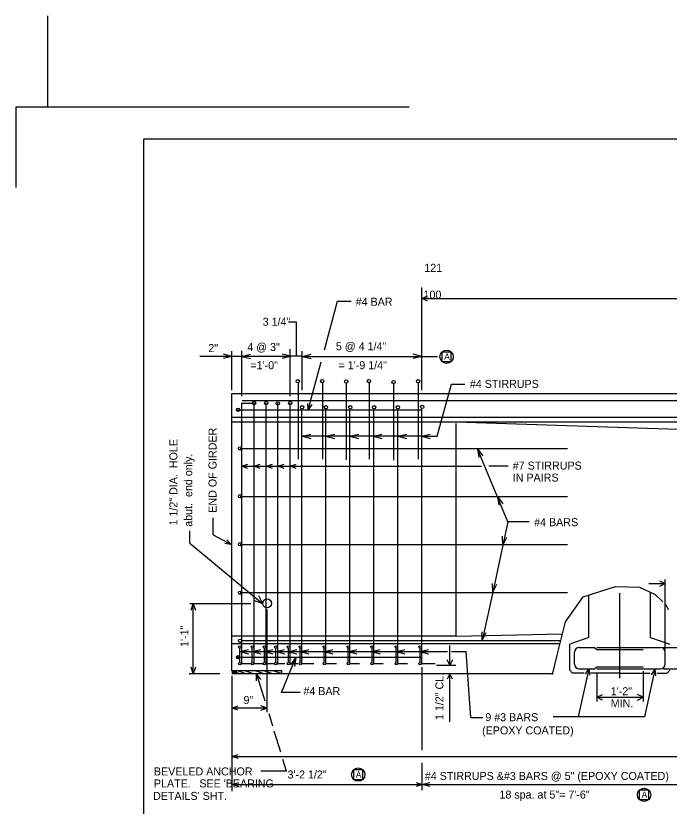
# Model space of a CAD drawing. Extents: x 1005.2 to 1101.8, y 2006.5 to 2073.7.
# Drawn here: x 1008.43 to 1035.67, y 2040.78 to 2073.7 of the extents above; entities that cross this region are included whole.
import ezdxf

# ---------------------------------------------------------------- set-up
doc = ezdxf.new("R2010")
doc.units = 0
for name, color, linetype in [('Level 1', 7, 'Continuous'), ('Level 2', 7, 'Continuous'), ('Level 5', 7, 'Continuous'), ('Level 6', 7, 'Continuous'), ('Level 60', 7, 'Continuous')]:
    doc.layers.add(name, color=color, linetype=linetype)

msp = doc.modelspace()

# ---------------------------------------------------------------- linework, layer by layer
at = {"layer": 'Level 1'}
for p, q in [((1024.831, 2069.894), (1008.43, 2069.894)), ((1008.43, 2069.894), (1008.43, 2066.554)), ((1013.763, 2012.562), (1013.763, 2068.561)), ((1097.431, 2068.561), (1013.763, 2068.561))]:
    msp.add_line(p, q, dxfattribs=at)
at = {"layer": 'Level 2'}
for p, q in [((1009.763, 2069.894), (1009.763, 2073.698)), ((1025.357, 2058.113), (1025.357, 2062.376)), ((1021.298, 2059.783), (1021.846, 2061.808)), ((1021.846, 2061.808), (1022.41, 2061.808)), ((1025.357, 2061.923), (1054.324, 2061.923)), ((1020.13, 2060.939), (1019.792, 2060.939)), ((1020.13, 2059.522), (1020.13, 2060.939)), ((1019.87, 2057.862), (1019.87, 2059.809)), ((1017.857, 2059.514), (1016.107, 2059.514)), ((1017.441, 2059.514), (1016.171, 2059.514)), ((1017.441, 2059.514), (1017.081, 2059.604)), ((1017.441, 2059.514), (1017.081, 2059.424)), ((1017.441, 2058.106), (1017.441, 2059.732)), ((1017.857, 2057.854), (1017.857, 2059.744)), ((1017.857, 2059.514), (1018.217, 2059.604)), ((1019.87, 2059.514), (1017.857, 2059.514)), ((1017.857, 2059.514), (1018.217, 2059.424)), ((1019.898, 2059.522), (1019.538, 2059.612)), ((1019.898, 2059.522), (1019.538, 2059.432)), ((1020.36, 2059.522), (1019.87, 2059.522)), ((1020.36, 2058.103), (1020.36, 2059.725)), ((1020.36, 2059.514), (1026.005, 2059.514)), ((1020.375, 2059.514), (1020.735, 2059.604)), ((1020.375, 2059.514), (1020.735, 2059.424)), ((1025.357, 2059.514), (1024.997, 2059.604)), ((1025.357, 2059.514), (1024.997, 2059.424)), ((1020.621, 2057.286), (1021.163, 2059.286)), ((1026.195, 2059.303), (1026.195, 2059.303)), ((1020.194, 2058.425), (1020.194, 2055.229)), ((1021.21, 2058.425), (1021.21, 2055.229)), ((1022.207, 2058.404), (1022.207, 2055.208)), ((1023.161, 2058.425), (1023.161, 2055.229)), ((1024.178, 2058.383), (1024.178, 2055.187)), ((1025.195, 2058.425), (1025.195, 2055.229)), ((1025.994, 2056.185), (1026.584, 2058.362)), ((1026.584, 2058.362), (1027.147, 2058.362)), ((1017.441, 2046.413), (1017.441, 2057.969)), ((1017.441, 2057.969), (1038.737, 2057.969)), ((1017.857, 2057.562), (1018.382, 2057.562)), ((1017.857, 2047.379), (1017.857, 2057.562)), ((1017.863, 2057.676), (1031.429, 2057.676)), ((1018.362, 2046.728), (1018.362, 2057.562)), ((1018.87, 2046.728), (1018.87, 2057.562)), ((1019.357, 2046.728), (1019.357, 2057.562)), ((1019.87, 2046.728), (1019.87, 2057.562)), ((1031.429, 2057.676), (1038.745, 2057.676)), ((1017.64, 2057.286), (1025.357, 2057.286)), ((1020.357, 2046.728), (1020.357, 2057.335)), ((1021.357, 2046.728), (1021.357, 2057.335)), ((1022.357, 2046.728), (1022.357, 2057.325)), ((1023.357, 2046.728), (1023.357, 2057.335)), ((1024.357, 2046.728), (1024.357, 2057.325)), ((1025.357, 2046.728), (1025.357, 2057.335)), ((1038.745, 2056.969), (1017.439, 2056.969)), ((1038.737, 2056.772), (1017.426, 2056.772)), ((1038.441, 2056.386), (1026.782, 2056.772)), ((1026.782, 2047.859), (1026.782, 2056.719)), ((1020.374, 2056.185), (1020.734, 2056.275)), ((1022.351, 2056.185), (1020.374, 2056.185)), ((1020.374, 2056.185), (1020.734, 2056.095)), ((1021.349, 2056.185), (1021.709, 2056.275)), ((1021.349, 2056.185), (1021.709, 2056.095)), ((1022.351, 2056.185), (1022.711, 2056.275)), ((1023.284, 2056.185), (1022.351, 2056.185)), ((1022.351, 2056.185), (1022.711, 2056.095)), ((1023.333, 2056.185), (1023.284, 2056.185)), ((1023.333, 2056.185), (1023.693, 2056.275)), ((1024.362, 2056.185), (1023.333, 2056.185)), ((1023.333, 2056.185), (1023.693, 2056.095)), ((1024.362, 2056.185), (1024.722, 2056.275)), ((1025.347, 2056.185), (1024.362, 2056.185)), ((1024.362, 2056.185), (1024.722, 2056.095)), ((1025.347, 2056.185), (1025.707, 2056.275)), ((1025.347, 2056.185), (1025.994, 2056.185)), ((1025.347, 2056.185), (1025.707, 2056.095)), ((1017.78, 2055.676), (1031.429, 2055.676)), ((1028.945, 2052.627), (1027.669, 2055.663)), ((1027.669, 2055.663), (1027.892, 2055.366)), ((1027.669, 2055.663), (1027.726, 2055.296)), ((1017.842, 2054.936), (1027.842, 2054.936)), ((1028.958, 2054.936), (1028.149, 2054.936)), ((1017.78, 2053.676), (1031.429, 2053.676)), ((1028.504, 2053.676), (1028.726, 2053.379)), ((1028.504, 2053.676), (1028.561, 2053.31)), ((1016.66, 2052.086), (1016.66, 2052.795)), ((1028.945, 2052.627), (1028.735, 2051.653)), ((1029.834, 2052.627), (1028.945, 2052.627)), ((1016.66, 2052.086), (1017.41, 2051.679)), ((1028.735, 2051.653), (1028.723, 2052.024)), ((1028.735, 2051.653), (1028.899, 2051.986)), ((1017.78, 2051.676), (1031.429, 2051.676)), ((1028.735, 2051.653), (1028.311, 2049.688)), ((1035.494, 2047.271), (1035.494, 2050.224)), ((1028.311, 2049.688), (1028.299, 2050.059)), ((1028.311, 2049.688), (1028.475, 2050.021)), ((1034.813, 2050.053), (1035.494, 2050.053)), ((1017.78, 2049.676), (1023.804, 2049.676)), ((1023.804, 2049.676), (1031.429, 2049.676)), ((1028.311, 2049.688), (1027.876, 2047.676)), ((1032.321, 2047.81), (1032.321, 2049.575)), ((1033.607, 2046.105), (1033.607, 2049.645)), ((1034.892, 2047.81), (1034.892, 2049.686)), ((1026.782, 2047.859), (1031.222, 2047.964)), ((1027.876, 2047.676), (1027.864, 2048.047)), ((1027.876, 2047.676), (1028.04, 2048.009)), ((1026.782, 2047.859), (1017.441, 2047.859)), ((1017.85, 2047.676), (1031.149, 2047.676)), ((1032.321, 2047.81), (1031.518, 2047.528)), ((1034.892, 2047.81), (1035.695, 2047.528)), ((1017.44, 2047.552), (1031.118, 2047.552)), ((1017.769, 2046.782), (1017.769, 2047.355)), ((1017.769, 2047.216), (1018.129, 2047.306)), ((1017.857, 2046.728), (1017.857, 2047.379)), ((1018.28, 2047.216), (1018.64, 2047.306)), ((1018.284, 2046.782), (1018.284, 2047.355)), ((1018.789, 2047.216), (1019.149, 2047.306)), ((1018.793, 2046.782), (1018.793, 2047.355)), ((1019.265, 2047.216), (1019.625, 2047.306)), ((1019.271, 2046.782), (1019.271, 2047.355)), ((1019.79, 2047.215), (1020.15, 2047.305)), ((1019.793, 2046.782), (1019.793, 2047.355)), ((1020.283, 2047.216), (1020.643, 2047.306)), ((1020.286, 2046.782), (1020.286, 2047.355)), ((1021.289, 2046.782), (1021.289, 2047.355)), ((1021.29, 2047.216), (1021.65, 2047.306)), ((1022.289, 2046.782), (1022.289, 2047.379)), ((1022.289, 2047.216), (1022.649, 2047.306)), ((1023.258, 2047.216), (1023.618, 2047.306)), ((1023.278, 2046.782), (1023.278, 2047.379)), ((1024.289, 2046.782), (1024.289, 2047.379)), ((1024.289, 2047.216), (1024.649, 2047.306)), ((1025.274, 2047.22), (1025.634, 2047.31)), ((1025.284, 2046.782), (1025.284, 2047.379)), ((1026.512, 2047.469), (1026.512, 2046.649)), ((1031.518, 2046.444), (1031.518, 2047.528)), ((1031.912, 2047.388), (1032.556, 2047.388)), ((1032.556, 2047.388), (1032.651, 2047.311)), ((1032.651, 2047.388), (1035.302, 2047.388)), ((1032.651, 2047.311), (1034.583, 2047.311)), ((1035.41, 2047.388), (1037.062, 2047.388)), ((1017.64, 2046.986), (1025.357, 2046.986)), ((1017.769, 2047.216), (1018.53, 2047.216)), ((1017.769, 2047.216), (1018.129, 2047.126)), ((1018.28, 2047.216), (1018.64, 2047.126)), ((1018.53, 2047.216), (1019.251, 2047.216)), ((1018.789, 2047.216), (1019.149, 2047.126)), ((1019.251, 2047.216), (1020.274, 2047.216)), ((1019.265, 2047.216), (1019.625, 2047.126)), ((1019.499, 2045.521), (1020.103, 2046.973)), ((1019.79, 2047.215), (1020.15, 2047.125)), ((1020.099, 2046.971), (1019.877, 2046.673)), ((1020.099, 2046.971), (1020.043, 2046.604)), ((1020.274, 2047.216), (1021.29, 2047.216)), ((1020.283, 2047.216), (1020.643, 2047.126)), ((1021.29, 2047.216), (1023.258, 2047.216)), ((1021.29, 2047.216), (1021.65, 2047.126)), ((1022.289, 2047.216), (1022.649, 2047.126)), ((1023.258, 2047.216), (1025.358, 2047.216)), ((1023.258, 2047.216), (1023.618, 2047.126)), ((1024.289, 2047.216), (1024.649, 2047.126)), ((1025.274, 2047.22), (1025.634, 2047.13)), ((1025.358, 2047.216), (1026.419, 2047.216)), ((1026.595, 2047.216), (1027.202, 2047.216)), ((1027.399, 2044.471), (1027.202, 2047.216)), ((1031.719, 2046.697), (1031.719, 2047.195)), ((1035.494, 2046.697), (1035.494, 2047.195)), ((1017.857, 2046.728), (1017.857, 2046.765)), ((1017.857, 2046.728), (1018.202, 2046.728)), ((1018.362, 2046.728), (1018.706, 2046.728)), ((1018.87, 2046.728), (1019.174, 2046.728)), ((1019.357, 2046.728), (1019.648, 2046.728)), ((1019.87, 2046.728), (1020.186, 2046.728)), ((1020.357, 2046.728), (1020.851, 2046.728)), ((1021.357, 2046.728), (1021.793, 2046.728)), ((1022.359, 2046.728), (1022.762, 2046.728)), ((1023.357, 2046.728), (1023.743, 2046.728)), ((1024.364, 2046.728), (1024.762, 2046.728)), ((1025.357, 2046.728), (1025.906, 2046.728)), ((1025.97, 2046.649), (1026.774, 2046.649)), ((1032.556, 2046.504), (1032.651, 2046.587)), ((1032.651, 2046.587), (1034.583, 2046.587)), ((1017.441, 2046.413), (1017.769, 2046.301)), ((1017.769, 2046.302), (1030.816, 2046.302)), ((1025.357, 2046.576), (1025.357, 2043.109)), ((1026.512, 2046.302), (1026.512, 2044.294)), ((1026.834, 2046.302), (1026.901, 2046.302)), ((1031.639, 2046.323), (1031.518, 2046.444)), ((1032.126, 2046.323), (1031.639, 2046.323)), ((1032.311, 2046.503), (1031.873, 2044.502)), ((1031.912, 2046.504), (1032.556, 2046.504)), ((1033.607, 2046.323), (1032.385, 2046.323)), ((1032.651, 2046.504), (1035.302, 2046.504)), ((1032.651, 2046.326), (1032.651, 2045.141)), ((1033.607, 2046.323), (1034.875, 2046.323)), ((1034.583, 2046.409), (1034.583, 2045.141)), ((1035.062, 2046.474), (1034.63, 2044.502)), ((1035.156, 2046.323), (1035.575, 2046.323)), ((1035.43, 2046.504), (1037.062, 2046.504)), ((1035.575, 2046.323), (1035.695, 2046.444)), ((1017.441, 2046.208), (1017.441, 2041.404)), ((1020.283, 2045.521), (1019.499, 2045.521)), ((1032.651, 2045.319), (1034.583, 2045.319)), ((1027.399, 2044.471), (1027.892, 2044.471)), ((1034.63, 2044.502), (1030.834, 2044.502)), ((1017.441, 2042.85), (1061.731, 2042.85)), ((1025.357, 2042.592), (1025.357, 2041.445)), ((1017.463, 2041.684), (1025.357, 2041.684)), ((1022.511, 2041.897), (1022.511, 2041.897)), ((1025.357, 2041.684), (1037.408, 2041.684)), ((1034.424, 2041.056), (1034.424, 2041.056))]:
    msp.add_line(p, q, dxfattribs=at)
for points in [[(1025.59, 2061.815), (1025.368, 2061.926), (1025.59, 2062.037)], [(1020.772, 2057.507), (1020.621, 2057.286), (1020.603, 2057.553)], [(1018.095, 2054.848), (1017.842, 2054.936), (1018.095, 2055.024)], [(1018.614, 2054.848), (1018.361, 2054.936), (1018.614, 2055.024)], [(1019.123, 2054.848), (1018.87, 2054.936), (1019.123, 2055.024)], [(1019.611, 2054.848), (1019.357, 2054.936), (1019.611, 2055.024)], [(1020.123, 2054.848), (1019.87, 2054.936), (1020.123, 2055.024)], [(1017.229, 2051.877), (1017.41, 2051.679), (1017.145, 2051.723)], [(1030.807, 2046.261), (1030.995, 2047.069), (1031.348, 2048.459), (1032.076, 2049.496), (1033.422, 2049.93), (1034.422, 2049.9), (1035.084, 2049.599), (1035.406, 2049.287)], [(1035.256, 2050.172), (1035.494, 2050.053), (1035.256, 2049.934)], [(1035.636, 2048.954), (1035.532, 2049.167)], [(1026.628, 2046.869), (1026.517, 2046.647), (1026.406, 2046.869)], [(1026.634, 2046.071), (1026.523, 2046.293), (1026.411, 2046.071)], [(1032.171, 2046.274), (1032.311, 2046.503), (1032.343, 2046.237)], [(1034.922, 2046.245), (1035.062, 2046.474), (1035.093, 2046.207)], [(1032.889, 2045.2), (1032.651, 2045.319), (1032.889, 2045.438)], [(1034.345, 2045.2), (1034.583, 2045.319), (1034.345, 2045.438)], [(1017.694, 2042.763), (1017.441, 2042.85), (1017.694, 2042.938)], [(1017.724, 2041.597), (1017.471, 2041.684), (1017.724, 2041.772)], [(1025.124, 2041.772), (1025.378, 2041.684), (1025.124, 2041.597)], [(1025.691, 2041.601), (1025.357, 2041.684), (1025.691, 2041.768)]]:
    msp.add_lwpolyline(points, dxfattribs=at)
for points in [[(1026.191, 2059.694), (1026.191, 2059.302), (1026.583, 2059.302), (1026.583, 2059.694)], [(1022.506, 2042.288), (1022.506, 2041.895), (1022.898, 2041.895), (1022.898, 2042.288)], [(1034.419, 2041.447), (1034.419, 2041.055), (1034.812, 2041.055), (1034.812, 2041.447)]]:
    msp.add_lwpolyline(points, close=True, dxfattribs=at)
for centre, radius in [((1026.388, 2059.499), 0.277), ((1020.184, 2058.477), 0.0694), ((1021.203, 2058.487), 0.0694), ((1022.202, 2058.467), 0.0694), ((1023.149, 2058.487), 0.0694), ((1024.178, 2058.446), 0.0694), ((1025.198, 2058.477), 0.0694), ((1018.362, 2057.568), 0.0694), ((1018.871, 2057.568), 0.0694), ((1019.352, 2057.558), 0.0694), ((1019.871, 2057.568), 0.0694), ((1020.36, 2057.397), 0.0694), ((1021.358, 2057.397), 0.0694), ((1022.372, 2057.397), 0.0694), ((1023.366, 2057.397), 0.0694), ((1024.359, 2057.397), 0.0694), ((1025.375, 2057.408), 0.0694), ((1017.697, 2057.288), 0.0694), ((1017.781, 2055.681), 0.0694), ((1017.781, 2053.689), 0.0694), ((1017.781, 2051.688), 0.0694), ((1017.781, 2049.669), 0.0694), ((1017.781, 2047.668), 0.0694), ((1017.767, 2047.407), 0.052), ((1018.287, 2047.407), 0.052), ((1018.796, 2047.407), 0.052), ((1019.269, 2047.407), 0.052), ((1019.796, 2047.407), 0.052), ((1020.287, 2047.407), 0.052), ((1021.291, 2047.407), 0.052), ((1022.291, 2047.407), 0.052), ((1023.274, 2047.407), 0.052), ((1024.291, 2047.407), 0.052), ((1025.286, 2047.407), 0.052), ((1017.697, 2046.984), 0.0694), ((1017.767, 2046.713), 0.052), ((1018.287, 2046.713), 0.052), ((1018.796, 2046.713), 0.052), ((1019.269, 2046.713), 0.052), ((1019.796, 2046.713), 0.052), ((1020.287, 2046.713), 0.052), ((1021.291, 2046.713), 0.052), ((1022.291, 2046.713), 0.052), ((1023.282, 2046.713), 0.052), ((1024.291, 2046.713), 0.052), ((1025.286, 2046.713), 0.052), ((1022.703, 2042.093), 0.277), ((1034.617, 2041.252), 0.277)]:
    msp.add_circle(centre, radius, dxfattribs=at)
for centre, start, end in [((1031.912, 2047.195), 90, 180), ((1035.302, 2047.195), 0, 90), ((1031.912, 2046.697), 180, 270), ((1035.302, 2046.697), 270, 0)]:
    msp.add_arc(centre, 0.193, start, end, dxfattribs=at)
at = {"layer": 'Level 5'}
for p, q in [((1015.685, 2051.734), (1015.685, 2052.253)), ((1015.685, 2051.734), (1018.731, 2049.207)), ((1018.731, 2049.207), (1018.349, 2049.352)), ((1018.731, 2049.207), (1018.562, 2049.539)), ((1018.232, 2049.203), (1015.688, 2049.203)), ((1015.829, 2046.311), (1015.829, 2049.201)), ((1018.888, 2048.97), (1018.888, 2044.7)), ((1016.94, 2046.287), (1015.65, 2046.287)), ((1018.888, 2044.867), (1017.441, 2044.867))]:
    msp.add_line(p, q, dxfattribs=at)
for points in [[(1015.741, 2048.948), (1015.829, 2049.201), (1015.916, 2048.948)], [(1015.741, 2048.948), (1015.829, 2049.201), (1015.916, 2048.948)], [(1015.916, 2046.565), (1015.829, 2046.311), (1015.741, 2046.565)], [(1017.694, 2044.779), (1017.441, 2044.867), (1017.694, 2044.955)], [(1018.641, 2044.779), (1018.894, 2044.867), (1018.641, 2044.955)]]:
    msp.add_lwpolyline(points, dxfattribs=at)
msp.add_circle((1018.906, 2049.225), 0.186, dxfattribs=at)
at = {"layer": 'Level 6'}
for p, q in [((1017.609, 2046.413), (1017.441, 2046.413)), ((1017.441, 2046.405), (1017.609, 2046.405)), ((1017.441, 2046.395), (1017.609, 2046.395)), ((1017.441, 2046.385), (1017.609, 2046.385)), ((1017.441, 2046.375), (1017.609, 2046.375)), ((1017.441, 2046.365), (1017.609, 2046.365)), ((1017.441, 2046.355), (1017.609, 2046.355)), ((1017.441, 2046.345), (1017.609, 2046.345)), ((1017.441, 2046.335), (1017.609, 2046.335)), ((1017.441, 2046.325), (1017.609, 2046.325)), ((1017.441, 2046.315), (1017.609, 2046.315)), ((1017.441, 2046.305), (1017.609, 2046.305)), ((1017.609, 2046.302), (1017.441, 2046.302)), ((1017.698, 2046.413), (1018.025, 2046.302)), ((1017.999, 2046.413), (1018.327, 2046.301)), ((1018.44, 2046.41), (1018.768, 2046.299)), ((1018.466, 2046.274), (1018.807, 2045.167)), ((1018.803, 2046.413), (1019.131, 2046.302)), ((1019.188, 2046.415), (1019.515, 2046.304)), ((1018.971, 2044.637), (1019.126, 2044.131)), ((1019.191, 2043.92), (1019.463, 2043.037)), ((1019.71, 2042.235), (1019.559, 2042.725)), ((1019.71, 2042.235), (1018.642, 2042.235))]:
    msp.add_line(p, q, dxfattribs=at)
msp.add_lwpolyline([(1019.518, 2046.413), (1017.609, 2046.413), (1017.609, 2046.302), (1019.518, 2046.302)], close=True, dxfattribs=at)
msp.add_lwpolyline([(1018.457, 2046.006), (1018.466, 2046.274), (1018.625, 2046.058)], dxfattribs=at)

# ---------------------------------------------------------------- texts
at = {"layer": 'Level 2'}
for s, height, p in [('#4 BAR', 0.3333, (1022.597, 2061.623)), ('3 1/4"', 0.3333, (1018.72, 2060.79)), ('4 @ 3"', 0.3333, (1018.079, 2059.738)), ('5 @ 4 1/4"', 0.3333, (1021.773, 2059.767)), ('2"', 0.3333, (1016.454, 2059.691)), ('A', 0.261, (1026.288, 2059.374)), ('=1\'-0"', 0.3333, (1018.209, 2058.979)), ('= 1\'-9 1/4"', 0.33333, (1021.882, 2058.979)), ('#4 STIRRUPS', 0.33333, (1027.357, 2058.2)), ('#7 STIRRUPS', 0.33333, (1029.145, 2054.799)), ('IN PAIRS', 0.3333, (1029.145, 2054.299)), ('#4 BARS', 0.3333, (1030.036, 2052.441)), ('#4 BAR', 0.3333, (1020.418, 2045.406)), ('1\'-2"', 0.3333, (1033.228, 2045.4)), ('MIN.', 0.3333, (1033.228, 2044.9)), ('9 #3 BARS', 0.3333, (1028, 2044.319)), ('(EPOXY COATED)', 0.33333, (1027.867, 2043.77)), ('3\'-2 1/2"', 0.3333, (1019.756, 2041.933)), ('A', 0.261, (1022.603, 2041.967)), ('#4 STIRRUPS &#3 BARS @ 5" (EPOXY COATED)', 0.33333, (1025.48, 2041.872)), ('18 spa. at 5"= 7\'-6"', 0.33333, (1028.59, 2041.097)), ('A', 0.261, (1034.517, 2041.127))]:
    msp.add_text(s, height=height, dxfattribs=at).set_placement(p)
for s, height, p in [('END OF GIRDER', 0.33333, (1016.797, 2053.001)), ('1 1/2" CL.', 0.3333, (1026.254, 2044.367))]:
    msp.add_text(s, height=height, rotation=90, dxfattribs=at).set_placement(p)
at = {"layer": 'Level 5'}
for s, height, p in [('1 1/2" DIA.  HOLE', 0.33333, (1015.167, 2052.47)), ('abut.  end only.', 0.33333, (1015.783, 2052.417)), ('1\'-1"', 0.3333, (1015.626, 2047.411))]:
    msp.add_text(s, height=height, rotation=90, dxfattribs=at).set_placement(p)
msp.add_text('9"', height=0.3333, dxfattribs=at).set_placement((1017.92, 2045.033))
at = {"layer": 'Level 6'}
for s, height, p in [('BEVELED ANCHOR', 0.33333, (1014.186, 2042.061)), ('PLATE.', 0.3333, (1014.186, 2041.561)), ("SEE 'BEARING", 0.33333, (1016.081, 2041.561)), ("DETAILS' SHT.", 0.33333, (1014.151, 2041.042))]:
    msp.add_text(s, height=height, dxfattribs=at).set_placement(p)
at = {"layer": 'Level 60'}
for s, p in [('121', (1025.457, 2063.035)), ('100', (1025.425, 2061.918))]:
    msp.add_text(s, height=0.3333, dxfattribs=at).set_placement(p)

doc.saveas('drawing.dxf')
